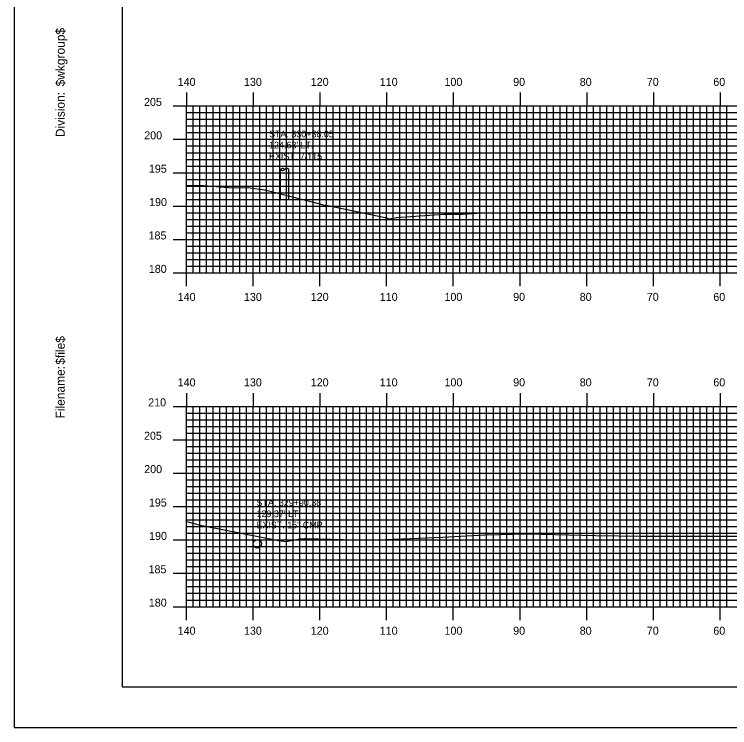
# Model space of a CAD drawing. Extents: x 1822392 to 1822735, y 442591 to 442811.
# Drawn here: x 1822392 to 1822499.2, y 442590.5 to 442697.4 of the extents above; entities that cross this region are included whole.
import ezdxf

# ---------------------------------------------------------------- set-up
doc = ezdxf.new("R2010")
doc.units = 0
for name, color, linetype in [('BORDER', 7, 'Continuous'), ('D_Drainage_Culvert', 7, 'Continuous'), ('D_Text_Monospaced', 7, 'Continuous'), ('H_V ANNOTATION', 7, 'Continuous'), ('MAJOR', 7, 'Continuous'), ('MINOR', 7, 'Continuous'), ('PLOT BOUNDARY', 7, 'Continuous'), ('S_Roadway_Centerline', 7, 'Continuous'), ('S_Utilities_Pole_Power', 7, 'Continuous')]:
    doc.layers.add(name, color=color, linetype=linetype)

msp = doc.modelspace()

# ---------------------------------------------------------------- linework, layer by layer
at = {"layer": 'BORDER'}
msp.add_lwpolyline([(1822408.17, 442596.67), (1822728.17, 442596.67), (1822728.17, 442806.67), (1822408.17, 442806.67)], close=True, dxfattribs=at)
at = {"layer": 'D_Drainage_Culvert'}
msp.add_circle((1822428.4, 442618.08), 0.625, dxfattribs=at)
at = {"layer": 'MAJOR'}
for p, q in [((1822417.77, 442685.67), (1822417.77, 442683.67)), ((1822427.77, 442685.67), (1822427.77, 442683.67)), ((1822437.77, 442685.67), (1822437.77, 442683.67)), ((1822447.77, 442685.67), (1822447.77, 442683.67)), ((1822457.77, 442685.67), (1822457.77, 442683.67)), ((1822467.77, 442685.67), (1822467.77, 442683.67)), ((1822477.77, 442685.67), (1822477.77, 442683.67)), ((1822487.77, 442685.67), (1822487.77, 442683.67)), ((1822497.77, 442685.67), (1822497.77, 442683.67)), ((1822415.77, 442683.67), (1822417.77, 442683.67)), ((1822417.77, 442683.67), (1822697.77, 442683.67)), ((1822417.77, 442658.67), (1822417.77, 442683.67)), ((1822417.77, 442658.67), (1822417.77, 442683.67)), ((1822417.77, 442683.67), (1822697.77, 442683.67)), ((1822427.77, 442658.67), (1822427.77, 442683.67)), ((1822437.77, 442658.67), (1822437.77, 442683.67)), ((1822447.77, 442658.67), (1822447.77, 442683.67)), ((1822457.77, 442658.67), (1822457.77, 442683.67)), ((1822467.77, 442658.67), (1822467.77, 442683.67)), ((1822477.77, 442658.67), (1822477.77, 442683.67)), ((1822487.77, 442658.67), (1822487.77, 442683.67)), ((1822497.77, 442658.67), (1822497.77, 442683.67)), ((1822415.77, 442678.67), (1822417.77, 442678.67)), ((1822417.77, 442678.67), (1822697.77, 442678.67)), ((1822415.77, 442673.67), (1822417.77, 442673.67)), ((1822417.77, 442673.67), (1822697.77, 442673.67)), ((1822415.77, 442668.67), (1822417.77, 442668.67)), ((1822417.77, 442668.67), (1822697.77, 442668.67)), ((1822415.77, 442663.67), (1822417.77, 442663.67)), ((1822417.77, 442663.67), (1822697.77, 442663.67)), ((1822415.77, 442658.67), (1822417.77, 442658.67)), ((1822417.77, 442658.67), (1822697.77, 442658.67)), ((1822417.77, 442658.67), (1822697.77, 442658.67)), ((1822417.77, 442656.66), (1822417.77, 442658.67)), ((1822427.77, 442656.66), (1822427.77, 442658.67)), ((1822437.77, 442656.66), (1822437.77, 442658.67)), ((1822447.77, 442656.66), (1822447.77, 442658.67)), ((1822457.77, 442656.66), (1822457.77, 442658.67)), ((1822467.77, 442656.66), (1822467.77, 442658.67)), ((1822477.77, 442656.66), (1822477.77, 442658.67)), ((1822487.77, 442656.66), (1822487.77, 442658.67)), ((1822497.77, 442656.66), (1822497.77, 442658.67)), ((1822417.77, 442640.67), (1822417.77, 442638.67)), ((1822427.77, 442640.67), (1822427.77, 442638.67)), ((1822437.77, 442640.67), (1822437.77, 442638.67)), ((1822447.77, 442640.67), (1822447.77, 442638.67)), ((1822457.77, 442640.67), (1822457.77, 442638.67)), ((1822467.77, 442640.67), (1822467.77, 442638.67)), ((1822477.77, 442640.67), (1822477.77, 442638.67)), ((1822487.77, 442640.67), (1822487.77, 442638.67)), ((1822497.77, 442640.67), (1822497.77, 442638.67)), ((1822415.77, 442638.67), (1822417.77, 442638.67)), ((1822417.77, 442638.67), (1822697.77, 442638.67)), ((1822417.77, 442608.67), (1822417.77, 442638.67)), ((1822417.77, 442608.67), (1822417.77, 442638.67)), ((1822417.77, 442638.67), (1822697.77, 442638.67)), ((1822427.77, 442608.67), (1822427.77, 442638.67)), ((1822437.77, 442608.67), (1822437.77, 442638.67)), ((1822447.77, 442608.67), (1822447.77, 442638.67)), ((1822457.77, 442608.67), (1822457.77, 442638.67)), ((1822467.77, 442608.67), (1822467.77, 442638.67)), ((1822477.77, 442608.67), (1822477.77, 442638.67)), ((1822487.77, 442608.67), (1822487.77, 442638.67)), ((1822497.77, 442608.67), (1822497.77, 442638.67)), ((1822415.77, 442633.67), (1822417.77, 442633.67)), ((1822417.77, 442633.67), (1822697.77, 442633.67)), ((1822415.77, 442628.67), (1822417.77, 442628.67)), ((1822417.77, 442628.67), (1822697.77, 442628.67)), ((1822415.77, 442623.67), (1822417.77, 442623.67)), ((1822417.77, 442623.67), (1822697.77, 442623.67)), ((1822415.77, 442618.67), (1822417.77, 442618.67)), ((1822417.77, 442618.67), (1822697.77, 442618.67)), ((1822415.77, 442613.67), (1822417.77, 442613.67)), ((1822417.77, 442613.67), (1822697.77, 442613.67)), ((1822415.77, 442608.67), (1822417.77, 442608.67)), ((1822417.77, 442608.67), (1822697.77, 442608.67)), ((1822417.77, 442608.67), (1822697.77, 442608.67)), ((1822417.77, 442606.66), (1822417.77, 442608.67)), ((1822427.77, 442606.66), (1822427.77, 442608.67)), ((1822437.77, 442606.66), (1822437.77, 442608.67)), ((1822447.77, 442606.66), (1822447.77, 442608.67)), ((1822457.77, 442606.66), (1822457.77, 442608.67)), ((1822467.77, 442606.66), (1822467.77, 442608.67)), ((1822477.77, 442606.66), (1822477.77, 442608.67)), ((1822487.77, 442606.66), (1822487.77, 442608.67)), ((1822497.77, 442606.66), (1822497.77, 442608.67))]:
    msp.add_line(p, q, dxfattribs=at)
at = {"layer": 'MINOR'}
for p, q in [((1822418.77, 442658.67), (1822418.77, 442683.67)), ((1822419.77, 442658.67), (1822419.77, 442683.67)), ((1822420.77, 442658.67), (1822420.77, 442683.67)), ((1822421.77, 442658.67), (1822421.77, 442683.67)), ((1822422.77, 442658.67), (1822422.77, 442683.67)), ((1822423.77, 442658.67), (1822423.77, 442683.67)), ((1822424.77, 442658.67), (1822424.77, 442683.67)), ((1822425.77, 442658.67), (1822425.77, 442683.67)), ((1822426.77, 442658.67), (1822426.77, 442683.67)), ((1822428.77, 442658.67), (1822428.77, 442683.67)), ((1822429.77, 442658.67), (1822429.77, 442683.67)), ((1822430.77, 442658.67), (1822430.77, 442683.67)), ((1822431.77, 442658.67), (1822431.77, 442683.67)), ((1822432.77, 442658.67), (1822432.77, 442683.67)), ((1822433.77, 442658.67), (1822433.77, 442683.67)), ((1822434.77, 442658.67), (1822434.77, 442683.67)), ((1822435.77, 442658.67), (1822435.77, 442683.67)), ((1822436.77, 442658.67), (1822436.77, 442683.67)), ((1822438.77, 442658.67), (1822438.77, 442683.67)), ((1822439.77, 442658.67), (1822439.77, 442683.67)), ((1822440.77, 442658.67), (1822440.77, 442683.67)), ((1822441.77, 442658.67), (1822441.77, 442683.67)), ((1822442.77, 442658.67), (1822442.77, 442683.67)), ((1822443.77, 442658.67), (1822443.77, 442683.67)), ((1822444.77, 442658.67), (1822444.77, 442683.67)), ((1822445.77, 442658.67), (1822445.77, 442683.67)), ((1822446.77, 442658.67), (1822446.77, 442683.67)), ((1822448.77, 442658.67), (1822448.77, 442683.67)), ((1822449.77, 442658.67), (1822449.77, 442683.67)), ((1822450.77, 442658.67), (1822450.77, 442683.67)), ((1822451.77, 442658.67), (1822451.77, 442683.67)), ((1822452.77, 442658.67), (1822452.77, 442683.67)), ((1822453.77, 442658.67), (1822453.77, 442683.67)), ((1822454.77, 442658.67), (1822454.77, 442683.67)), ((1822455.77, 442658.67), (1822455.77, 442683.67)), ((1822456.77, 442658.67), (1822456.77, 442683.67)), ((1822458.77, 442658.67), (1822458.77, 442683.67)), ((1822459.77, 442658.67), (1822459.77, 442683.67)), ((1822460.77, 442658.67), (1822460.77, 442683.67)), ((1822461.77, 442658.67), (1822461.77, 442683.67)), ((1822462.77, 442658.67), (1822462.77, 442683.67)), ((1822463.77, 442658.67), (1822463.77, 442683.67)), ((1822464.77, 442658.67), (1822464.77, 442683.67)), ((1822465.77, 442658.67), (1822465.77, 442683.67)), ((1822466.77, 442658.67), (1822466.77, 442683.67)), ((1822468.77, 442658.67), (1822468.77, 442683.67)), ((1822469.77, 442658.67), (1822469.77, 442683.67)), ((1822470.77, 442658.67), (1822470.77, 442683.67)), ((1822471.77, 442658.67), (1822471.77, 442683.67)), ((1822472.77, 442658.67), (1822472.77, 442683.67)), ((1822473.77, 442658.67), (1822473.77, 442683.67)), ((1822474.77, 442658.67), (1822474.77, 442683.67)), ((1822475.77, 442658.67), (1822475.77, 442683.67)), ((1822476.77, 442658.67), (1822476.77, 442683.67)), ((1822478.77, 442658.67), (1822478.77, 442683.67)), ((1822479.77, 442658.67), (1822479.77, 442683.67)), ((1822480.77, 442658.67), (1822480.77, 442683.67)), ((1822481.77, 442658.67), (1822481.77, 442683.67)), ((1822482.77, 442658.67), (1822482.77, 442683.67)), ((1822483.77, 442658.67), (1822483.77, 442683.67)), ((1822484.77, 442658.67), (1822484.77, 442683.67)), ((1822485.77, 442658.67), (1822485.77, 442683.67)), ((1822486.77, 442658.67), (1822486.77, 442683.67)), ((1822488.77, 442658.67), (1822488.77, 442683.67)), ((1822489.77, 442658.67), (1822489.77, 442683.67)), ((1822490.77, 442658.67), (1822490.77, 442683.67)), ((1822491.77, 442658.67), (1822491.77, 442683.67)), ((1822492.77, 442658.67), (1822492.77, 442683.67)), ((1822493.77, 442658.67), (1822493.77, 442683.67)), ((1822494.77, 442658.67), (1822494.77, 442683.67)), ((1822495.77, 442658.67), (1822495.77, 442683.67)), ((1822496.77, 442658.67), (1822496.77, 442683.67)), ((1822498.77, 442658.67), (1822498.77, 442683.67)), ((1822417.77, 442682.67), (1822697.77, 442682.67)), ((1822417.77, 442682.67), (1822419.77, 442682.67)), ((1822417.77, 442681.67), (1822697.77, 442681.67)), ((1822417.77, 442681.67), (1822419.77, 442681.67)), ((1822417.77, 442680.67), (1822697.77, 442680.67)), ((1822417.77, 442680.67), (1822419.77, 442680.67)), ((1822417.77, 442679.67), (1822697.77, 442679.67)), ((1822417.77, 442679.67), (1822419.77, 442679.67)), ((1822417.77, 442677.67), (1822697.77, 442677.67)), ((1822417.77, 442677.67), (1822419.77, 442677.67)), ((1822417.77, 442676.67), (1822697.77, 442676.67)), ((1822417.77, 442676.67), (1822419.77, 442676.67)), ((1822417.77, 442675.67), (1822697.77, 442675.67)), ((1822417.77, 442675.67), (1822419.77, 442675.67)), ((1822417.77, 442674.67), (1822697.77, 442674.67)), ((1822417.77, 442674.67), (1822419.77, 442674.67)), ((1822417.77, 442672.67), (1822697.77, 442672.67)), ((1822417.77, 442672.67), (1822419.77, 442672.67)), ((1822417.77, 442671.67), (1822697.77, 442671.67)), ((1822417.77, 442671.67), (1822419.77, 442671.67)), ((1822417.77, 442670.67), (1822697.77, 442670.67)), ((1822417.77, 442670.67), (1822419.77, 442670.67)), ((1822417.77, 442669.67), (1822697.77, 442669.67)), ((1822417.77, 442669.67), (1822419.77, 442669.67)), ((1822417.77, 442667.67), (1822697.77, 442667.67)), ((1822417.77, 442667.67), (1822419.77, 442667.67)), ((1822417.77, 442666.67), (1822697.77, 442666.67)), ((1822417.77, 442666.67), (1822419.77, 442666.67)), ((1822417.77, 442665.67), (1822697.77, 442665.67)), ((1822417.77, 442665.67), (1822419.77, 442665.67)), ((1822417.77, 442664.67), (1822697.77, 442664.67)), ((1822417.77, 442664.67), (1822419.77, 442664.67)), ((1822417.77, 442662.67), (1822697.77, 442662.67)), ((1822417.77, 442662.67), (1822419.77, 442662.67)), ((1822417.77, 442661.67), (1822697.77, 442661.67)), ((1822417.77, 442661.67), (1822419.77, 442661.67)), ((1822417.77, 442660.67), (1822697.77, 442660.67)), ((1822417.77, 442660.67), (1822419.77, 442660.67)), ((1822417.77, 442659.67), (1822697.77, 442659.67)), ((1822417.77, 442659.67), (1822419.77, 442659.67)), ((1822418.77, 442608.67), (1822418.77, 442638.67)), ((1822419.77, 442608.67), (1822419.77, 442638.67)), ((1822420.77, 442608.67), (1822420.77, 442638.67)), ((1822421.77, 442608.67), (1822421.77, 442638.67)), ((1822422.77, 442608.67), (1822422.77, 442638.67)), ((1822423.77, 442608.67), (1822423.77, 442638.67)), ((1822424.77, 442608.67), (1822424.77, 442638.67)), ((1822425.77, 442608.67), (1822425.77, 442638.67)), ((1822426.77, 442608.67), (1822426.77, 442638.67)), ((1822428.77, 442608.67), (1822428.77, 442638.67)), ((1822429.77, 442608.67), (1822429.77, 442638.67)), ((1822430.77, 442608.67), (1822430.77, 442638.67)), ((1822431.77, 442608.67), (1822431.77, 442638.67)), ((1822432.77, 442608.67), (1822432.77, 442638.67)), ((1822433.77, 442608.67), (1822433.77, 442638.67)), ((1822434.77, 442608.67), (1822434.77, 442638.67)), ((1822435.77, 442608.67), (1822435.77, 442638.67)), ((1822436.77, 442608.67), (1822436.77, 442638.67)), ((1822438.77, 442608.67), (1822438.77, 442638.67)), ((1822439.77, 442608.67), (1822439.77, 442638.67)), ((1822440.77, 442608.67), (1822440.77, 442638.67)), ((1822441.77, 442608.67), (1822441.77, 442638.67)), ((1822442.77, 442608.67), (1822442.77, 442638.67)), ((1822443.77, 442608.67), (1822443.77, 442638.67)), ((1822444.77, 442608.67), (1822444.77, 442638.67)), ((1822445.77, 442608.67), (1822445.77, 442638.67)), ((1822446.77, 442608.67), (1822446.77, 442638.67)), ((1822448.77, 442608.67), (1822448.77, 442638.67)), ((1822449.77, 442608.67), (1822449.77, 442638.67)), ((1822450.77, 442608.67), (1822450.77, 442638.67)), ((1822451.77, 442608.67), (1822451.77, 442638.67)), ((1822452.77, 442608.67), (1822452.77, 442638.67)), ((1822453.77, 442608.67), (1822453.77, 442638.67)), ((1822454.77, 442608.67), (1822454.77, 442638.67)), ((1822455.77, 442608.67), (1822455.77, 442638.67)), ((1822456.77, 442608.67), (1822456.77, 442638.67)), ((1822458.77, 442608.67), (1822458.77, 442638.67)), ((1822459.77, 442608.67), (1822459.77, 442638.67)), ((1822460.77, 442608.67), (1822460.77, 442638.67)), ((1822461.77, 442608.67), (1822461.77, 442638.67)), ((1822462.77, 442608.67), (1822462.77, 442638.67)), ((1822463.77, 442608.67), (1822463.77, 442638.67)), ((1822464.77, 442608.67), (1822464.77, 442638.67)), ((1822465.77, 442608.67), (1822465.77, 442638.67)), ((1822466.77, 442608.67), (1822466.77, 442638.67)), ((1822468.77, 442608.67), (1822468.77, 442638.67)), ((1822469.77, 442608.67), (1822469.77, 442638.67)), ((1822470.77, 442608.67), (1822470.77, 442638.67)), ((1822471.77, 442608.67), (1822471.77, 442638.67)), ((1822472.77, 442608.67), (1822472.77, 442638.67)), ((1822473.77, 442608.67), (1822473.77, 442638.67)), ((1822474.77, 442608.67), (1822474.77, 442638.67)), ((1822475.77, 442608.67), (1822475.77, 442638.67)), ((1822476.77, 442608.67), (1822476.77, 442638.67)), ((1822478.77, 442608.67), (1822478.77, 442638.67)), ((1822479.77, 442608.67), (1822479.77, 442638.67)), ((1822480.77, 442608.67), (1822480.77, 442638.67)), ((1822481.77, 442608.67), (1822481.77, 442638.67)), ((1822482.77, 442608.67), (1822482.77, 442638.67)), ((1822483.77, 442608.67), (1822483.77, 442638.67)), ((1822484.77, 442608.67), (1822484.77, 442638.67)), ((1822485.77, 442608.67), (1822485.77, 442638.67)), ((1822486.77, 442608.67), (1822486.77, 442638.67)), ((1822488.77, 442608.67), (1822488.77, 442638.67)), ((1822489.77, 442608.67), (1822489.77, 442638.67)), ((1822490.77, 442608.67), (1822490.77, 442638.67)), ((1822491.77, 442608.67), (1822491.77, 442638.67)), ((1822492.77, 442608.67), (1822492.77, 442638.67)), ((1822493.77, 442608.67), (1822493.77, 442638.67)), ((1822494.77, 442608.67), (1822494.77, 442638.67)), ((1822495.77, 442608.67), (1822495.77, 442638.67)), ((1822496.77, 442608.67), (1822496.77, 442638.67)), ((1822498.77, 442608.67), (1822498.77, 442638.67)), ((1822417.77, 442637.67), (1822697.77, 442637.67)), ((1822417.77, 442637.67), (1822419.77, 442637.67)), ((1822417.77, 442636.67), (1822697.77, 442636.67)), ((1822417.77, 442636.67), (1822419.77, 442636.67)), ((1822417.77, 442635.67), (1822697.77, 442635.67)), ((1822417.77, 442635.67), (1822419.77, 442635.67)), ((1822417.77, 442634.67), (1822697.77, 442634.67)), ((1822417.77, 442634.67), (1822419.77, 442634.67)), ((1822417.77, 442632.67), (1822697.77, 442632.67)), ((1822417.77, 442632.67), (1822419.77, 442632.67)), ((1822417.77, 442631.67), (1822697.77, 442631.67)), ((1822417.77, 442631.67), (1822419.77, 442631.67)), ((1822417.77, 442630.67), (1822697.77, 442630.67)), ((1822417.77, 442630.67), (1822419.77, 442630.67)), ((1822417.77, 442629.67), (1822697.77, 442629.67)), ((1822417.77, 442629.67), (1822419.77, 442629.67)), ((1822417.77, 442627.67), (1822697.77, 442627.67)), ((1822417.77, 442627.67), (1822419.77, 442627.67)), ((1822417.77, 442626.67), (1822697.77, 442626.67)), ((1822417.77, 442626.67), (1822419.77, 442626.67)), ((1822417.77, 442625.67), (1822697.77, 442625.67)), ((1822417.77, 442625.67), (1822419.77, 442625.67)), ((1822417.77, 442624.67), (1822697.77, 442624.67)), ((1822417.77, 442624.67), (1822419.77, 442624.67)), ((1822417.77, 442622.67), (1822697.77, 442622.67)), ((1822417.77, 442622.67), (1822419.77, 442622.67)), ((1822417.77, 442621.67), (1822697.77, 442621.67)), ((1822417.77, 442621.67), (1822419.77, 442621.67)), ((1822417.77, 442620.67), (1822697.77, 442620.67)), ((1822417.77, 442620.67), (1822419.77, 442620.67)), ((1822417.77, 442619.67), (1822697.77, 442619.67)), ((1822417.77, 442619.67), (1822419.77, 442619.67)), ((1822417.77, 442617.67), (1822697.77, 442617.67)), ((1822417.77, 442617.67), (1822419.77, 442617.67)), ((1822417.77, 442616.67), (1822697.77, 442616.67)), ((1822417.77, 442616.67), (1822419.77, 442616.67)), ((1822417.77, 442615.67), (1822697.77, 442615.67)), ((1822417.77, 442615.67), (1822419.77, 442615.67)), ((1822417.77, 442614.67), (1822697.77, 442614.67)), ((1822417.77, 442614.67), (1822419.77, 442614.67)), ((1822417.77, 442612.67), (1822697.77, 442612.67)), ((1822417.77, 442612.67), (1822419.77, 442612.67)), ((1822417.77, 442611.67), (1822697.77, 442611.67)), ((1822417.77, 442611.67), (1822419.77, 442611.67)), ((1822417.77, 442610.67), (1822697.77, 442610.67)), ((1822417.77, 442610.67), (1822419.77, 442610.67)), ((1822417.77, 442609.67), (1822697.77, 442609.67)), ((1822417.77, 442609.67), (1822419.77, 442609.67))]:
    msp.add_line(p, q, dxfattribs=at)
at = {"layer": 'PLOT BOUNDARY'}
msp.add_lwpolyline([(1822391.98, 442590.55), (1822731.98, 442590.55), (1822731.98, 442810.55), (1822391.98, 442810.55)], close=True, dxfattribs=at)
at = {"layer": 'S_Roadway_Centerline'}
for points in [[(1822417.77, 442671.74), (1822418.76, 442671.74), (1822419.46, 442671.77), (1822420.34, 442671.73), (1822424.13, 442671.45), (1822427.34, 442671.39), (1822429.47, 442671.08), (1822429.93, 442671.02), (1822430.12, 442670.97), (1822436.44, 442669.37), (1822438.62, 442668.78), (1822438.68, 442668.81), (1822438.74, 442668.8), (1822447.79, 442666.89), (1822448.18, 442666.77), (1822449.28, 442666.95), (1822456.36, 442667.46), (1822458.83, 442667.47), (1822459.18, 442667.45), (1822462.12, 442667.66), (1822472.97, 442667.77), (1822486.49, 442667.73), (1822489.55, 442667.65), (1822491.47, 442667.64), (1822499.1, 442667.66), (1822505.18, 442667.66)], [(1822417.77, 442621.42), (1822419.14, 442621.09), (1822419.85, 442620.9), (1822420.65, 442620.73), (1822431.57, 442618.6), (1822432.72, 442618.41), (1822434.78, 442618.82), (1822435.42, 442618.86), (1822435.57, 442618.86), (1822445.16, 442618.61), (1822456.21, 442619.09), (1822462.51, 442619.43), (1822468.94, 442619.57), (1822479.12, 442619.33), (1822485.89, 442619.22), (1822489.21, 442619.21), (1822502.32, 442619.22)]]:
    msp.add_lwpolyline(points, dxfattribs=at)
at = {"layer": 'S_Utilities_Pole_Power'}
for p, q in [((1822431.89, 442674.16), (1822432.05, 442674.27)), ((1822432.36, 442674.27), (1822432.51, 442674.16)), ((1822432.67, 442674.27), (1822432.51, 442674.16)), ((1822433.14, 442674.16), (1822432.98, 442674.27)), ((1822431.89, 442669.54), (1822431.89, 442674.16)), ((1822432.05, 442674.05), (1822431.89, 442674.16)), ((1822432.51, 442674.16), (1822432.36, 442674.05)), ((1822433.14, 442669.54), (1822433.14, 442674.16))]:
    msp.add_line(p, q, dxfattribs=at)
for centre, start, end in [((1822432.2, 442674.05), 90, 125.2644), ((1822432.2, 442674.05), 54.7356, 90), ((1822432.83, 442674.05), 90, 125.2644), ((1822432.83, 442674.05), 54.7356, 90), ((1822432.2, 442674.27), 234.7356, 270), ((1822432.2, 442674.27), 270, 305.2644)]:
    msp.add_arc(centre, 0.271, start, end, dxfattribs=at)

# ---------------------------------------------------------------- texts
at = {"layer": 'BORDER'}
for s, p in [('$wkgroup$', (1822399.54, 442686.6)), ('Division:', (1822399.54, 442679)), ('$file$', (1822399.54, 442644.92)), ('Filename:', (1822399.54, 442636.86))]:
    msp.add_text(s, height=1.339, rotation=90, dxfattribs=at).set_placement(p)
at = {"layer": 'D_Text_Monospaced'}
for s, p in [('STA. 330+38.05', (1822430.16, 442678.98)), ("124.63' LT.", (1822430.16, 442677.31)), ('EXIST. 7/115', (1822430.16, 442675.63)), ('STA. 329+90.38', (1822428.28, 442623.75)), ("129.37' LT.", (1822428.28, 442622.08)), ('EXIST. 15" CMP', (1822428.28, 442620.4))]:
    msp.add_text(s, height=1, dxfattribs=at).set_placement(p)
at = {"layer": 'H_V ANNOTATION'}
for s, p in [('140', (1822416.47, 442686.67)), ('130', (1822426.4, 442686.67)), ('120', (1822436.41, 442686.67)), ('110', (1822446.75, 442686.67)), ('100', (1822456.45, 442686.67)), ('90', (1822466.74, 442686.67)), ('80', (1822476.72, 442686.67)), ('70', (1822486.77, 442686.67)), ('60', (1822496.74, 442686.67)), ('205', (1822411.42, 442683.67)), ('200', (1822411.45, 442678.67)), ('195', (1822412.15, 442673.67)), ('190', (1822412.18, 442668.67)), ('185', (1822412.1, 442663.67)), ('180', (1822412.14, 442658.67)), ('140', (1822416.47, 442654.47)), ('130', (1822426.4, 442654.47)), ('120', (1822436.41, 442654.47)), ('110', (1822446.75, 442654.47)), ('100', (1822456.45, 442654.47)), ('90', (1822466.74, 442654.47)), ('80', (1822476.72, 442654.47)), ('70', (1822486.77, 442654.47)), ('60', (1822496.74, 442654.47)), ('140', (1822416.47, 442641.67)), ('130', (1822426.4, 442641.67)), ('120', (1822436.41, 442641.67)), ('110', (1822446.75, 442641.67)), ('100', (1822456.45, 442641.67)), ('90', (1822466.74, 442641.67)), ('80', (1822476.72, 442641.67)), ('70', (1822486.77, 442641.67)), ('60', (1822496.74, 442641.67)), ('210', (1822412.05, 442638.67)), ('205', (1822411.42, 442633.67)), ('200', (1822411.45, 442628.67)), ('195', (1822412.15, 442623.67)), ('190', (1822412.18, 442618.67)), ('185', (1822412.1, 442613.67)), ('180', (1822412.14, 442608.67)), ('140', (1822416.47, 442604.47)), ('130', (1822426.4, 442604.47)), ('120', (1822436.41, 442604.47)), ('110', (1822446.75, 442604.47)), ('100', (1822456.45, 442604.47)), ('90', (1822466.74, 442604.47)), ('80', (1822476.72, 442604.47)), ('70', (1822486.77, 442604.47)), ('60', (1822496.74, 442604.47))]:
    msp.add_text(s, height=1.2, dxfattribs=at).set_placement(p)
at = {"layer": 'MAJOR'}
for p in [(1822417.76, 442658.67), (1822417.76, 442608.67)]:
    msp.add_text('-', height=0.012, dxfattribs=at).set_placement(p)

doc.saveas('drawing.dxf')
